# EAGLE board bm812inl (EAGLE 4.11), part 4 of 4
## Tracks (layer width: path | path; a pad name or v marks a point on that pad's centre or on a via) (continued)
N$167 (continued)
  Bottom 0.254: 107.99,116.19 98.46,116.19 97.51,117.14 C14.K1 | 107.99,116.19 108.94,117.14 C13.K1 | 120.69,116.19 121.64,117.14 C12.K1 | 120.69,116.19 107.99,116.19 | 133.39,116.19 134.34,117.14 C11.K1 | 133.39,116.19 120.69,116.19 | 146.09,116.19 147.04,117.14 C10.K1 | 146.09,116.19 133.39,116.19 | 158.79,116.19 159.74,117.14 C09.K1 | 146.09,116.19 158.79,116.19 | 171.49,116.19 172.44,117.14 C08.K1 | 158.79,116.19 171.49,116.19 | 184.19,116.19 185.14,117.14 C07.K1 | 171.49,116.19 184.19,116.19 | 196.89,116.19 197.84,117.14 C06.K1 | 184.19,116.19 196.89,116.19 | 209.59,116.19 210.54,117.14 C05.K1 | 196.89,116.19 209.59,116.19 | 222.29,116.19 223.24,117.14 C04.K1 | 209.59,116.19 222.29,116.19 | 234.99,116.19 235.94,117.14 C03.K1 | 222.29,116.19 234.99,116.19 | 247.69,116.19 248.64,117.14 C02.K1 | 234.99,116.19 247.69,116.19 | 247.69,116.19 260.39,116.19 261.34,117.14 C01.K1
N$168
  Bottom 0.254: 101.64,118.73 96.24,118.73 95.6,118.1 91.48,118.1 91.16,117.78 C14.K2 | 101.64,118.73 102.59,117.78 C13.K2 | 114.34,118.73 115.29,117.78 C12.K2 | 114.34,118.73 101.64,118.73 | 127.04,118.73 127.99,117.78 C11.K2 | 127.04,118.73 114.34,118.73 | 139.74,118.73 140.69,117.78 C10.K2 | 139.74,118.73 127.04,118.73 | 152.44,118.73 153.39,117.78 C09.K2 | 139.74,118.73 152.44,118.73 | 165.14,118.73 166.09,117.78 C08.K2 | 152.44,118.73 165.14,118.73 | 177.84,118.73 178.79,117.78 C07.K2 | 165.14,118.73 177.84,118.73 | 190.54,118.73 191.49,117.78 C06.K2 | 177.84,118.73 190.54,118.73 | 203.24,118.73 204.19,117.78 C05.K2 | 190.54,118.73 203.24,118.73 | 215.94,118.73 216.89,117.78 C04.K2 | 203.24,118.73 215.94,118.73 | 228.64,118.73 229.59,117.78 C03.K2 | 215.94,118.73 228.64,118.73 | 241.34,118.73 242.29,117.78 C02.K2 | 228.64,118.73 241.34,118.73 | 241.34,118.73 254.04,118.73 254.99,117.78 C01.K2
N$169
  Bottom 0.254: 104.81,113.02 95.29,113.02 94.33,113.97 C14.L1 | 104.81,113.02 105.76,113.97 C13.L1 | 117.51,113.02 118.46,113.97 C12.L1 | 117.51,113.02 104.81,113.02 | 130.21,113.02 131.16,113.97 C11.L1 | 130.21,113.02 117.51,113.02 | 142.91,113.02 143.86,113.97 C10.L1 | 142.91,113.02 130.21,113.02 | 155.61,113.02 156.56,113.97 C09.L1 | 142.91,113.02 155.61,113.02 | 168.31,113.02 169.26,113.97 C08.L1 | 155.61,113.02 168.31,113.02 | 181.01,113.02 181.96,113.97 C07.L1 | 168.31,113.02 181.01,113.02 | 193.71,113.02 194.66,113.97 C06.L1 | 181.01,113.02 193.71,113.02 | 206.41,113.02 207.36,113.97 C05.L1 | 193.71,113.02 206.41,113.02 | 219.11,113.02 220.06,113.97 C04.L1 | 206.41,113.02 219.11,113.02 | 231.81,113.02 232.76,113.97 C03.L1 | 219.11,113.02 231.81,113.02 | 244.51,113.02 245.46,113.97 C02.L1 | 231.81,113.02 244.51,113.02 | 244.51,113.02 257.21,113.02 258.16,113.97 C01.L1
N$170
  Bottom 0.254: C14.L2 87.98,114.61 88.94,115.56 97.83,115.56 98.78,114.61 99.41,114.61 C13.L2 104.49,114.29 105.76,115.56 114.34,115.56 | 114.34,115.56 113.38,114.61 C12.L2 | 123.86,115.56 114.34,115.56 | 123.86,115.56 124.81,114.61 C11.L2 | 136.56,115.56 137.51,114.61 C10.L2 | 136.56,115.56 123.86,115.56 | 149.26,115.56 150.21,114.61 C09.L2 | 149.26,115.56 136.56,115.56 | 161.96,115.56 162.91,114.61 C08.L2 | 149.26,115.56 161.96,115.56 | 174.66,115.56 175.61,114.61 C07.L2 | 161.96,115.56 174.66,115.56 | 187.36,115.56 188.31,114.61 C06.L2 | 174.66,115.56 187.36,115.56 | 200.06,115.56 201.01,114.61 C05.L2 | 187.36,115.56 200.06,115.56 | 212.76,115.56 213.71,114.61 C04.L2 | 200.06,115.56 212.76,115.56 | 225.46,115.56 226.41,114.61 C03.L2 | 212.76,115.56 225.46,115.56 | 238.16,115.56 239.11,114.61 C02.L2 | 225.46,115.56 238.16,115.56 | 238.16,115.56 250.86,115.56 251.81,114.61 C01.L2
N$171
  Bottom 0.254: 107.99,109.84 98.46,109.84 97.51,110.8 C14.M1 | 107.99,109.84 108.94,110.8 C13.M1 | 120.69,109.84 121.64,110.8 C12.M1 | 120.69,109.84 107.99,109.84 | 133.39,109.84 134.34,110.8 C11.M1 | 133.39,109.84 120.69,109.84 | 146.09,109.84 147.04,110.8 C10.M1 | 146.09,109.84 133.39,109.84 | 158.79,109.84 159.74,110.8 C09.M1 | 146.09,109.84 158.79,109.84 | 171.49,109.84 172.44,110.8 C08.M1 | 158.79,109.84 171.49,109.84 | 184.19,109.84 185.14,110.8 C07.M1 | 171.49,109.84 184.19,109.84 | 196.89,109.84 197.84,110.8 C06.M1 | 184.19,109.84 196.89,109.84 | 209.59,109.84 210.54,110.8 C05.M1 | 196.89,109.84 209.59,109.84 | 222.29,109.84 223.24,110.8 C04.M1 | 209.59,109.84 222.29,109.84 | 234.99,109.84 235.94,110.8 C03.M1 | 222.29,109.84 234.99,109.84 | 247.69,109.84 248.64,110.8 C02.M1 | 234.99,109.84 247.69,109.84 | 247.69,109.84 260.39,109.84 261.34,110.8 C01.M1
N$172
  Bottom 0.254: 101.64,112.38 96.24,112.38 95.29,111.43 91.16,111.43 C14.M2 | 101.64,112.38 102.59,111.43 C13.M2 | 114.34,112.38 115.29,111.43 C12.M2 | 114.34,112.38 101.64,112.38 | 127.04,112.38 127.99,111.43 C11.M2 | 127.04,112.38 114.34,112.38 | 139.74,112.38 140.69,111.43 C10.M2 | 139.74,112.38 127.04,112.38 | 152.44,112.38 153.39,111.43 C09.M2 | 152.44,112.38 139.74,112.38 | 165.14,112.38 166.09,111.43 C08.M2 | 152.44,112.38 165.14,112.38 | 177.84,112.38 178.79,111.43 C07.M2 | 165.14,112.38 177.84,112.38 | 190.54,112.38 191.49,111.43 C06.M2 | 177.84,112.38 190.54,112.38 | 203.24,112.38 204.19,111.43 C05.M2 | 190.54,112.38 203.24,112.38 | 215.94,112.38 216.89,111.43 C04.M2 | 203.24,112.38 215.94,112.38 | 228.64,112.38 229.59,111.43 C03.M2 | 215.94,112.38 228.64,112.38 | 241.34,112.38 242.29,111.43 C02.M2 | 228.64,112.38 241.34,112.38 | 241.34,112.38 254.04,112.38 254.99,111.43 C01.M2
N$175
  Bottom 0.254: 107.99,103.49 98.46,103.49 97.51,104.44 C14.P1 | 107.99,103.49 108.94,104.44 C13.P1 | 120.69,103.49 121.64,104.44 C12.P1 | 120.69,103.49 107.99,103.49 | 133.39,103.49 134.34,104.44 C11.P1 | 133.39,103.49 120.69,103.49 | 146.09,103.49 147.04,104.44 C10.P1 | 146.09,103.49 133.39,103.49 | 158.79,103.49 159.74,104.44 C09.P1 | 158.79,103.49 146.09,103.49 | 171.49,103.49 172.44,104.44 C08.P1 | 158.79,103.49 171.49,103.49 | 184.19,103.49 185.14,104.44 C07.P1 | 171.49,103.49 184.19,103.49 | 196.89,103.49 197.84,104.44 C06.P1 | 184.19,103.49 196.89,103.49 | 209.59,103.49 210.54,104.44 C05.P1 | 196.89,103.49 209.59,103.49 | 222.29,103.49 223.24,104.44 C04.P1 | 209.59,103.49 222.29,103.49 | 234.99,103.49 235.94,104.44 C03.P1 | 222.29,103.49 234.99,103.49 | 247.69,103.49 248.64,104.44 C02.P1 | 234.99,103.49 247.69,103.49 | 247.69,103.49 260.39,103.49 261.34,104.44 C01.P1
N$176
  Bottom 0.254: 101.64,106.03 92.11,106.03 91.16,105.08 C14.P2 | 101.64,106.03 102.59,105.08 C13.P2 | 114.34,106.03 115.29,105.08 C12.P2 | 114.34,106.03 101.64,106.03 | 127.04,106.03 127.99,105.08 C11.P2 | 127.04,106.03 114.34,106.03 | 139.74,106.03 140.69,105.08 C10.P2 | 139.74,106.03 127.04,106.03 | 152.44,106.03 153.39,105.08 C09.P2 | 152.44,106.03 139.74,106.03 | 165.14,106.03 166.09,105.08 C08.P2 | 152.44,106.03 165.14,106.03 | 177.84,106.03 178.79,105.08 C07.P2 | 165.14,106.03 177.84,106.03 | 190.54,106.03 191.49,105.08 C06.P2 | 177.84,106.03 190.54,106.03 | 203.24,106.03 204.19,105.08 C05.P2 | 190.54,106.03 203.24,106.03 | 215.94,106.03 216.89,105.08 C04.P2 | 203.24,106.03 215.94,106.03 | 228.64,106.03 229.59,105.08 C03.P2 | 215.94,106.03 228.64,106.03 | 241.34,106.03 242.29,105.08 C02.P2 | 228.64,106.03 241.34,106.03 | 241.34,106.03 254.04,106.03 254.99,105.08 C01.P2
N$177
  Bottom 0.254: 104.81,100.32 95.29,100.32 94.33,101.27 C14.R1 | 104.81,100.32 105.76,101.27 C13.R1 | 117.51,100.32 118.46,101.27 C12.R1 | 117.51,100.32 104.81,100.32 | 130.21,100.32 131.16,101.27 C11.R1 | 130.21,100.32 117.51,100.32 | 142.91,100.32 143.86,101.27 C10.R1 | 142.91,100.32 130.21,100.32 | 155.61,100.32 156.56,101.27 C09.R1 | 155.61,100.32 142.91,100.32 | 168.31,100.32 169.26,101.27 C08.R1 | 155.61,100.32 168.31,100.32 | 181.01,100.32 181.96,101.27 C07.R1 | 168.31,100.32 181.01,100.32 | 193.71,100.32 194.66,101.27 C06.R1 | 181.01,100.32 193.71,100.32 | 206.41,100.32 207.36,101.27 C05.R1 | 193.71,100.32 206.41,100.32 | 219.11,100.32 220.06,101.27 C04.R1 | 206.41,100.32 219.11,100.32 | 231.81,100.32 232.76,101.27 C03.R1 | 219.11,100.32 231.81,100.32 | 244.51,100.32 245.46,101.27 C02.R1 | 231.81,100.32 244.51,100.32 | 244.51,100.32 257.21,100.32 258.16,101.27 C01.R1
N$178
  Bottom 0.254: 98.46,102.86 88.94,102.86 87.98,101.91 C14.R2 | 98.46,102.86 99.41,101.91 C13.R2 | 111.16,102.86 112.11,101.91 C12.R2 | 111.16,102.86 98.46,102.86 | 123.86,102.86 124.81,101.91 C11.R2 | 123.86,102.86 111.16,102.86 | 136.56,102.86 137.51,101.91 C10.R2 | 136.56,102.86 123.86,102.86 | 149.26,102.86 150.21,101.91 C09.R2 | 149.26,102.86 136.56,102.86 | 161.96,102.86 162.91,101.91 C08.R2 | 161.96,102.86 149.26,102.86 | 174.66,102.86 175.61,101.91 C07.R2 | 161.96,102.86 174.66,102.86 | 187.36,102.86 188.31,101.91 C06.R2 | 174.66,102.86 187.36,102.86 | 200.06,102.86 201.01,101.91 C05.R2 | 187.36,102.86 200.06,102.86 | 212.76,102.86 213.71,101.91 C04.R2 | 200.06,102.86 212.76,102.86 | 225.46,102.86 226.41,101.91 C03.R2 | 212.76,102.86 225.46,102.86 | 238.16,102.86 239.11,101.91 C02.R2 | 225.46,102.86 238.16,102.86 | 238.16,102.86 250.86,102.86 251.81,101.91 C01.R2
N$179
  Bottom 0.254: 107.99,97.14 98.46,97.14 97.51,98.1 C14.S1 | 107.99,97.14 108.94,98.1 C13.S1 | 120.69,97.14 121.64,98.1 C12.S1 | 120.69,97.14 107.99,97.14 | 133.39,97.14 134.34,98.1 C11.S1 | 133.39,97.14 120.69,97.14 | 146.09,97.14 147.04,98.1 C10.S1 | 146.09,97.14 133.39,97.14 | 158.79,97.14 159.74,98.1 C09.S1 | 158.79,97.14 146.09,97.14 | 171.49,97.14 172.44,98.1 C08.S1 | 158.79,97.14 171.49,97.14 | 184.19,97.14 185.14,98.1 C07.S1 | 171.49,97.14 184.19,97.14 | 196.89,97.14 197.84,98.1 C06.S1 | 184.19,97.14 196.89,97.14 | 209.59,97.14 210.54,98.1 C05.S1 | 196.89,97.14 209.59,97.14 | 222.29,97.14 223.24,98.1 C04.S1 | 209.59,97.14 222.29,97.14 | 234.99,97.14 235.94,98.1 C03.S1 | 222.29,97.14 234.99,97.14 | 247.69,97.14 248.64,98.1 C02.S1 | 234.99,97.14 247.69,97.14 | 247.69,97.14 260.39,97.14 261.34,98.1 C01.S1
N$180
  Bottom 0.254: 101.64,99.68 92.11,99.68 91.16,98.73 C14.S2 | 101.64,99.68 102.59,98.73 C13.S2 | 114.34,99.68 115.29,98.73 C12.S2 | 114.34,99.68 101.64,99.68 | 127.04,99.68 127.99,98.73 C11.S2 | 127.04,99.68 114.34,99.68 | 139.74,99.68 140.69,98.73 C10.S2 | 139.74,99.68 127.04,99.68 | 152.44,99.68 153.39,98.73 C09.S2 | 152.44,99.68 139.74,99.68 | 165.14,99.68 166.09,98.73 C08.S2 | 165.14,99.68 152.44,99.68 | 177.84,99.68 178.79,98.73 C07.S2 | 165.14,99.68 177.84,99.68 | 190.54,99.68 191.49,98.73 C06.S2 | 177.84,99.68 190.54,99.68 | 203.24,99.68 204.19,98.73 C05.S2 | 190.54,99.68 203.24,99.68 | 215.94,99.68 216.89,98.73 C04.S2 | 203.24,99.68 215.94,99.68 | 228.64,99.68 229.59,98.73 C03.S2 | 215.94,99.68 228.64,99.68 | 241.34,99.68 242.29,98.73 C02.S2 | 228.64,99.68 241.34,99.68 | 241.34,99.68 254.04,99.68 254.99,98.73 C01.S2
N$183
  Bottom 0.254: 107.99,90.79 98.46,90.79 97.51,91.74 C14.U1 | 107.99,90.79 108.94,91.74 C13.U1 | 120.69,90.79 121.64,91.74 C12.U1 | 120.69,90.79 107.99,90.79 | 133.39,90.79 134.34,91.74 C11.U1 | 133.39,90.79 120.69,90.79 | 146.09,90.79 147.04,91.74 C10.U1 | 146.09,90.79 133.39,90.79 | 158.79,90.79 159.74,91.74 C09.U1 | 158.79,90.79 146.09,90.79 | 171.49,90.79 172.44,91.74 C08.U1 | 171.49,90.79 158.79,90.79 | 184.19,90.79 185.14,91.74 C07.U1 | 171.49,90.79 184.19,90.79 | 196.89,90.79 197.84,91.74 C06.U1 | 184.19,90.79 196.89,90.79 | 209.59,90.79 210.54,91.74 C05.U1 | 196.89,90.79 209.59,90.79 | 222.29,90.79 223.24,91.74 C04.U1 | 209.59,90.79 222.29,90.79 | 234.99,90.79 235.94,91.74 C03.U1 | 222.29,90.79 234.99,90.79 | 247.69,90.79 248.64,91.74 C02.U1 | 234.99,90.79 247.69,90.79 | 247.69,90.79 260.39,90.79 261.34,91.74 C01.U1
N$184
  Bottom 0.254: 101.64,93.33 92.11,93.33 91.16,92.38 C14.U2 | 101.64,93.33 102.59,92.38 C13.U2 | 101.64,93.33 114.34,93.33 115.29,92.38 C12.U2 116.56,92.38 117.51,93.33 127.04,93.33 | 127.04,93.33 127.99,92.38 C11.U2 | 139.74,93.33 140.69,92.38 C10.U2 | 139.74,93.33 127.04,93.33 | 152.44,93.33 153.39,92.38 C09.U2 | 152.44,93.33 139.74,93.33 | 165.14,93.33 166.09,92.38 C08.U2 | 165.14,93.33 152.44,93.33 | 177.84,93.33 178.79,92.38 C07.U2 | 165.14,93.33 177.84,93.33 | 190.54,93.33 191.49,92.38 C06.U2 | 177.84,93.33 190.54,93.33 | 203.24,93.33 204.19,92.38 C05.U2 | 190.54,93.33 203.24,93.33 | 215.94,93.33 216.89,92.38 C04.U2 | 203.24,93.33 215.94,93.33 | 228.64,93.33 229.59,92.38 C03.U2 | 215.94,93.33 228.64,93.33 | 241.34,93.33 242.29,92.38 C02.U2 | 228.64,93.33 241.34,93.33 | 241.34,93.33 254.04,93.33 254.99,92.38 C01.U2
N$186
  Bottom 0.254: 104.81,87.62 95.29,87.62 94.33,88.57 C14.V1 | 104.81,87.62 105.76,88.57 C13.V1 | 117.51,87.62 118.46,88.57 C12.V1 | 117.51,87.62 104.81,87.62 | 130.21,87.62 131.16,88.57 C11.V1 | 130.21,87.62 117.51,87.62 | 142.91,87.62 143.86,88.57 C10.V1 | 142.91,87.62 130.21,87.62 | 155.61,87.62 156.56,88.57 C09.V1 | 155.61,87.62 142.91,87.62 | 168.31,87.62 169.26,88.57 C08.V1 | 168.31,87.62 155.61,87.62 | 181.01,87.62 181.96,88.57 C07.V1 | 168.31,87.62 181.01,87.62 | 193.71,87.62 194.66,88.57 C06.V1 | 181.01,87.62 193.71,87.62 | 206.41,87.62 207.36,88.57 C05.V1 | 193.71,87.62 206.41,87.62 | 219.11,87.62 220.06,88.57 C04.V1 | 206.41,87.62 219.11,87.62 | 231.81,87.62 232.76,88.57 C03.V1 | 219.11,87.62 231.81,87.62 | 244.51,87.62 245.46,88.57 C02.V1 | 231.81,87.62 244.51,87.62 | 244.51,87.62 257.21,87.62 258.16,88.57 C01.V1
N$187
  Bottom 0.254: 98.46,90.16 93.06,90.16 92.11,89.21 87.98,89.21 C14.V2 | 98.46,90.16 99.41,89.21 C13.V2 | 111.16,90.16 112.11,89.21 C12.V2 | 111.16,90.16 98.46,90.16 | 123.86,90.16 124.81,89.21 C11.V2 | 123.86,90.16 111.16,90.16 | 136.56,90.16 137.51,89.21 C10.V2 | 136.56,90.16 123.86,90.16 | 149.26,90.16 150.21,89.21 C09.V2 | 149.26,90.16 136.56,90.16 | 161.96,90.16 162.91,89.21 C08.V2 | 161.96,90.16 149.26,90.16 | 174.66,90.16 175.61,89.21 C07.V2 | 174.66,90.16 161.96,90.16 | 187.36,90.16 188.31,89.21 C06.V2 | 174.66,90.16 187.36,90.16 | 200.06,90.16 201.01,89.21 C05.V2 | 187.36,90.16 200.06,90.16 | 212.76,90.16 213.71,89.21 C04.V2 | 200.06,90.16 212.76,90.16 | 225.46,90.16 226.41,89.21 C03.V2 | 212.76,90.16 225.46,90.16 | 238.16,90.16 239.11,89.21 C02.V2 | 225.46,90.16 238.16,90.16 | 238.16,90.16 250.86,90.16 251.81,89.21 C01.V2
N$188
  Bottom 0.254: 107.99,74.28 98.46,74.28 97.51,73.33 D14.A1 | 107.99,74.28 108.94,73.33 D13.A1 | 120.69,74.28 121.64,73.33 D12.A1 | 120.69,74.28 107.99,74.28 | 133.39,74.28 134.34,73.33 D11.A1 | 133.39,74.28 120.69,74.28 | 146.09,74.28 147.04,73.33 D10.A1 | 146.09,74.28 133.39,74.28 | 158.79,74.28 159.74,73.33 D09.A1 | 158.79,74.28 146.09,74.28 | 158.79,74.28 171.49,74.28 172.44,73.33 D08.A1 173.71,72.69 174.66,71.74 184.19,71.74 | 184.19,71.74 185.14,72.69 D07.A1 | 196.89,71.74 197.84,72.69 D06.A1 | 184.19,71.74 196.89,71.74 | 196.89,71.74 209.59,71.74 210.54,72.69 D05.A1 211.81,73.33 212.76,74.28 222.29,74.28 | 222.29,74.28 223.24,73.33 D04.A1 | 234.99,74.28 235.94,73.33 D03.A1 | 222.29,74.28 234.99,74.28 | 247.69,74.28 248.64,73.33 D02.A1 | 234.99,74.28 247.69,74.28 | 247.69,74.28 260.39,74.28 261.34,73.33 D01.A1
N$190
  Bottom 0.254: 104.81,71.11 95.29,71.11 94.33,70.16 D14.B1 | 104.81,71.11 105.76,70.16 D13.B1 | 104.81,71.11 117.51,71.11 118.46,70.16 D12.B1 119.73,70.16 122.59,70.16 123.54,71.11 130.21,71.11 131.16,70.16 D11.B1 132.43,70.16 135.29,70.16 136.24,71.11 142.91,71.11 143.86,70.16 D10.B1 145.13,70.16 147.99,70.16 148.94,71.11 155.61,71.11 156.56,70.16 D09.B1 157.83,70.16 158.47,70.79 162.6,70.79 162.91,71.11 171.49,71.11 | 171.49,71.11 170.53,70.16 D08.B1 | 181.01,71.11 171.49,71.11 | 181.01,71.11 181.96,70.16 D07.B1 | 193.71,71.11 194.66,70.16 D06.B1 | 193.71,71.11 181.01,71.11 | 206.41,71.11 207.36,70.16 D05.B1 | 193.71,71.11 206.41,71.11 | 206.41,71.11 219.11,71.11 220.06,70.16 D04.B1 221.33,70.16 224.19,70.16 225.14,71.11 231.81,71.11 232.76,70.16 D03.B1 234.03,70.16 236.89,70.16 237.84,71.11 244.51,71.11 245.46,70.16 D02.B1 246.73,70.16 249.59,70.16 250.54,71.11 257.21,71.11 258.16,70.16 D01.B1
N$196
  Bottom 0.254: 98.46,64.76 88.94,64.76 87.98,63.81 D14.D2 | 98.46,64.76 99.41,63.81 D13.D2 | 111.16,64.76 112.11,63.81 D12.D2 | 111.16,64.76 98.46,64.76 | 123.86,64.76 124.81,63.81 D11.D2 | 123.86,64.76 111.16,64.76 | 136.56,64.76 137.51,63.81 D10.D2 | 136.56,64.76 123.86,64.76 | 136.56,64.76 149.26,64.76 150.21,63.81 D09.D2 151.48,63.81 152.44,64.76 161.96,64.76 | 161.96,64.76 162.91,63.81 D08.D2 | 174.66,64.76 175.61,63.81 D07.D2 | 174.66,64.76 161.96,64.76 | 187.36,64.76 188.31,63.81 D06.D2 | 187.36,64.76 174.66,64.76 | 200.06,64.76 201.01,63.81 D05.D2 | 200.06,64.76 187.36,64.76 | 212.76,64.76 213.71,63.81 D04.D2 | 200.06,64.76 212.76,64.76 | 225.46,64.76 226.41,63.81 D03.D2 | 212.76,64.76 225.46,64.76 | 238.16,64.76 239.11,63.81 D02.D2 | 225.46,64.76 238.16,64.76 | 238.16,64.76 250.86,64.76 251.81,63.81 D01.D2
N$198
  Bottom 0.254: 101.64,61.58 92.11,61.58 91.16,60.63 D14.E2 | 101.64,61.58 102.59,60.63 D13.E2 | 114.34,61.58 115.29,60.63 D12.E2 | 114.34,61.58 101.64,61.58 | 127.04,61.58 127.99,60.63 D11.E2 | 127.04,61.58 114.34,61.58 | 139.74,61.58 140.69,60.63 D10.E2 | 139.74,61.58 127.04,61.58 | 152.44,61.58 153.39,60.63 D09.E2 | 152.44,61.58 139.74,61.58 | 165.14,61.58 166.09,60.63 D08.E2 | 165.14,61.58 152.44,61.58 | 177.84,61.58 178.79,60.63 D07.E2 | 177.84,61.58 165.14,61.58 | 190.54,61.58 191.49,60.63 D06.E2 | 190.54,61.58 177.84,61.58 | 203.24,61.58 204.19,60.63 D05.E2 | 203.24,61.58 190.54,61.58 | 215.94,61.58 216.89,60.63 D04.E2 | 203.24,61.58 215.94,61.58 | 228.64,61.58 229.59,60.63 D03.E2 | 215.94,61.58 228.64,61.58 | 241.34,61.58 242.29,60.63 D02.E2 | 228.64,61.58 241.34,61.58 | 241.34,61.58 254.04,61.58 254.99,60.63 D01.E2
N$202
  Bottom 0.254: D14.H2 91.16,54.28 91.48,54.6 95.6,54.6 96.24,55.23 101.64,55.23 102.59,54.28 D13.H2 103.86,54.28 104.81,55.23 114.34,55.23 | 114.34,55.23 115.29,54.28 D12.H2 | 127.04,55.23 127.99,54.28 D11.H2 | 127.04,55.23 114.34,55.23 | 139.74,55.23 140.69,54.28 D10.H2 | 139.74,55.23 127.04,55.23 | 152.44,55.23 153.39,54.28 D09.H2 | 152.44,55.23 139.74,55.23 | 165.14,55.23 166.09,54.28 D08.H2 | 165.14,55.23 152.44,55.23 | 177.84,55.23 178.79,54.28 D07.H2 | 177.84,55.23 165.14,55.23 | 190.54,55.23 191.49,54.28 D06.H2 | 190.54,55.23 177.84,55.23 | 203.24,55.23 204.19,54.28 D05.H2 | 203.24,55.23 190.54,55.23 | 215.94,55.23 216.89,54.28 D04.H2 | 203.24,55.23 215.94,55.23 | 228.64,55.23 229.59,54.28 D03.H2 | 215.94,55.23 228.64,55.23 | 241.34,55.23 242.29,54.28 D02.H2 | 228.64,55.23 241.34,55.23 | 241.34,55.23 254.04,55.23 254.99,54.28 D01.H2
N$204
  Bottom 0.254: 98.46,52.06 88.94,52.06 87.98,51.1 D14.J2 | 98.46,52.06 99.41,51.1 D13.J2 | 111.16,52.06 112.11,51.1 D12.J2 | 111.16,52.06 98.46,52.06 | 123.86,52.06 124.81,51.1 D11.J2 | 123.86,52.06 111.16,52.06 | 136.56,52.06 137.51,51.1 D10.J2 | 136.56,52.06 123.86,52.06 | 149.26,52.06 150.21,51.1 D09.J2 | 149.26,52.06 136.56,52.06 | 161.96,52.06 162.91,51.1 D08.J2 | 161.96,52.06 149.26,52.06 | 174.66,52.06 175.61,51.1 D07.J2 | 174.66,52.06 161.96,52.06 | 187.36,52.06 188.31,51.1 D06.J2 | 187.36,52.06 174.66,52.06 | 200.06,52.06 201.01,51.1 D05.J2 | 200.06,52.06 187.36,52.06 | 212.76,52.06 213.71,51.1 D04.J2 | 212.76,52.06 200.06,52.06 | 225.46,52.06 226.41,51.1 D03.J2 | 212.76,52.06 225.46,52.06 | 238.16,52.06 239.11,51.1 D02.J2 | 225.46,52.06 238.16,52.06 | 238.16,52.06 250.86,52.06 251.81,51.1 D01.J2
N$206
  Bottom 0.254: 101.64,46.34 92.11,46.34 91.16,47.29 D14.K2 | 101.64,46.34 102.59,47.29 D13.K2 | 114.34,46.34 115.29,47.29 D12.K2 | 114.34,46.34 101.64,46.34 | 127.04,46.34 127.99,47.29 D11.K2 | 127.04,46.34 114.34,46.34 | 139.74,46.34 140.69,47.29 D10.K2 | 139.74,46.34 127.04,46.34 | 152.44,46.34 153.39,47.29 D09.K2 | 152.44,46.34 139.74,46.34 | 165.14,46.34 166.09,47.29 D08.K2 | 165.14,46.34 152.44,46.34 | 177.84,46.34 178.79,47.29 D07.K2 | 177.84,46.34 165.14,46.34 | 190.54,46.34 191.49,47.29 D06.K2 | 190.54,46.34 177.84,46.34 | 203.24,46.34 204.19,47.29 D05.K2 | 203.24,46.34 190.54,46.34 | 215.94,46.34 216.89,47.29 D04.K2 | 215.94,46.34 203.24,46.34 | 228.64,46.34 229.59,47.29 D03.K2 | 215.94,46.34 228.64,46.34 | 241.34,46.34 242.29,47.29 D02.K2 | 228.64,46.34 241.34,46.34 | 241.34,46.34 254.04,46.34 254.99,47.29 D01.K2
N$208
  Bottom 0.254: 98.46,45.71 88.94,45.71 87.98,44.75 D14.L2 | 98.46,45.71 99.41,44.75 D13.L2 | 111.16,45.71 112.11,44.75 D12.L2 | 111.16,45.71 98.46,45.71 | 123.86,45.71 124.81,44.75 D11.L2 | 123.86,45.71 111.16,45.71 | 136.56,45.71 137.51,44.75 D10.L2 | 136.56,45.71 123.86,45.71 | 149.26,45.71 150.21,44.75 D09.L2 | 149.26,45.71 136.56,45.71 | 161.96,45.71 162.91,44.75 D08.L2 | 161.96,45.71 149.26,45.71 | 174.66,45.71 175.61,44.75 D07.L2 | 174.66,45.71 161.96,45.71 | 187.36,45.71 188.31,44.75 D06.L2 | 187.36,45.71 174.66,45.71 | 200.06,45.71 201.01,44.75 D05.L2 | 200.06,45.71 187.36,45.71 | 212.76,45.71 213.71,44.75 D04.L2 | 212.76,45.71 200.06,45.71 | 225.46,45.71 226.41,44.75 D03.L2 | 212.76,45.71 225.46,45.71 | 238.16,45.71 239.11,44.75 D02.L2 | 225.46,45.71 238.16,45.71 | 238.16,45.71 250.86,45.71 251.81,44.75 D01.L2
N$210
  Bottom 0.254: 101.64,42.53 96.24,42.53 95.6,41.9 91.48,41.9 91.16,41.58 D14.M2 | 101.64,42.53 102.59,41.58 D13.M2 | 114.34,42.53 115.29,41.58 D12.M2 | 114.34,42.53 101.64,42.53 | 127.04,42.53 127.99,41.58 D11.M2 | 127.04,42.53 114.34,42.53 | 139.74,42.53 140.69,41.58 D10.M2 | 139.74,42.53 127.04,42.53 | 152.44,42.53 153.39,41.58 D09.M2 | 152.44,42.53 139.74,42.53 | 165.14,42.53 166.09,41.58 D08.M2 | 165.14,42.53 152.44,42.53 | 177.84,42.53 178.79,41.58 D07.M2 | 177.84,42.53 165.14,42.53 | 190.54,42.53 191.49,41.58 D06.M2 | 190.54,42.53 177.84,42.53 | 203.24,42.53 204.19,41.58 D05.M2 | 203.24,42.53 190.54,42.53 | 215.94,42.53 216.89,41.58 D04.M2 | 215.94,42.53 203.24,42.53 | 228.64,42.53 229.59,41.58 D03.M2 | 215.94,42.53 228.64,42.53 | 241.34,42.53 242.29,41.58 D02.M2 | 228.64,42.53 241.34,42.53 | 241.34,42.53 254.04,42.53 254.99,41.58 D01.M2
N$214
  Bottom 0.254: 101.64,36.18 92.11,36.18 91.16,35.23 D14.P2 | 101.64,36.18 102.59,35.23 D13.P2 | 101.64,36.18 114.34,36.18 115.29,35.23 D12.P2 116.56,35.23 116.88,35.55 121,35.55 121.64,36.18 130.21,36.18 | 130.21,36.18 129.26,35.23 D11.P2 | 139.74,36.18 130.21,36.18 | 139.74,36.18 140.69,35.23 D10.P2 | 152.44,36.18 153.39,35.23 D09.P2 | 152.44,36.18 139.74,36.18 | 165.14,36.18 166.09,35.23 D08.P2 | 165.14,36.18 152.44,36.18 | 177.84,36.18 178.79,35.23 D07.P2 | 177.84,36.18 165.14,36.18 | 190.54,36.18 191.49,35.23 D06.P2 | 190.54,36.18 177.84,36.18 | 203.24,36.18 204.19,35.23 D05.P2 | 203.24,36.18 190.54,36.18 | 215.94,36.18 216.89,35.23 D04.P2 | 215.94,36.18 203.24,36.18 | 228.64,36.18 229.59,35.23 D03.P2 | 228.64,36.18 215.94,36.18 | 241.34,36.18 242.29,35.23 D02.P2 | 228.64,36.18 241.34,36.18 | 241.34,36.18 254.04,36.18 254.99,35.23 D01.P2
N$215
  Bottom 0.254: 104.81,30.47 95.29,30.47 94.33,31.42 D14.R1 | 104.81,30.47 105.76,31.42 D13.R1 | 117.51,30.47 118.46,31.42 D12.R1 | 117.51,30.47 104.81,30.47 | 130.21,30.47 131.16,31.42 D11.R1 | 130.21,30.47 117.51,30.47 | 142.91,30.47 143.86,31.42 D10.R1 | 142.91,30.47 130.21,30.47 | 155.61,30.47 156.56,31.42 D09.R1 | 155.61,30.47 142.91,30.47 | 168.31,30.47 169.26,31.42 D08.R1 | 168.31,30.47 155.61,30.47 | 181.01,30.47 181.96,31.42 D07.R1 | 181.01,30.47 168.31,30.47 | 193.71,30.47 194.66,31.42 D06.R1 | 193.71,30.47 181.01,30.47 | 206.41,30.47 207.36,31.42 D05.R1 | 206.41,30.47 193.71,30.47 | 219.11,30.47 220.06,31.42 D04.R1 | 219.11,30.47 206.41,30.47 | 231.81,30.47 232.76,31.42 D03.R1 | 231.81,30.47 219.11,30.47 | 244.51,30.47 245.46,31.42 D02.R1 | 231.81,30.47 244.51,30.47 | 244.51,30.47 257.21,30.47 258.16,31.42 D01.R1
N$216
  Bottom 0.254: 98.46,33.01 88.94,33.01 87.98,32.06 D14.R2 | 98.46,33.01 99.41,32.06 D13.R2 | 111.16,33.01 112.11,32.06 D12.R2 | 111.16,33.01 98.46,33.01 | 123.86,33.01 124.81,32.06 D11.R2 | 123.86,33.01 111.16,33.01 | 136.56,33.01 137.51,32.06 D10.R2 | 136.56,33.01 123.86,33.01 | 149.26,33.01 150.21,32.06 D09.R2 | 149.26,33.01 136.56,33.01 | 161.96,33.01 162.91,32.06 D08.R2 | 161.96,33.01 149.26,33.01 | 174.66,33.01 175.61,32.06 D07.R2 | 174.66,33.01 161.96,33.01 | 187.36,33.01 188.31,32.06 D06.R2 | 187.36,33.01 174.66,33.01 | 200.06,33.01 201.01,32.06 D05.R2 | 200.06,33.01 187.36,33.01 | 212.76,33.01 213.71,32.06 D04.R2 | 212.76,33.01 200.06,33.01 | 225.46,33.01 226.41,32.06 D03.R2 | 225.46,33.01 212.76,33.01 | 238.16,33.01 239.11,32.06 D02.R2 | 225.46,33.01 238.16,33.01 | 238.16,33.01 250.86,33.01 251.81,32.06 D01.R2
N$218
  Bottom 0.254: 101.64,29.83 92.11,29.83 91.16,28.88 D14.S2 | 101.64,29.83 102.59,28.88 D13.S2 | 114.34,29.83 115.29,28.88 D12.S2 | 114.34,29.83 101.64,29.83 | 127.04,29.83 127.99,28.88 D11.S2 | 127.04,29.83 114.34,29.83 | 139.74,29.83 140.69,28.88 D10.S2 | 139.74,29.83 127.04,29.83 | 152.44,29.83 153.39,28.88 D09.S2 | 152.44,29.83 139.74,29.83 | 165.14,29.83 166.09,28.88 D08.S2 | 165.14,29.83 152.44,29.83 | 177.84,29.83 178.79,28.88 D07.S2 | 177.84,29.83 165.14,29.83 | 190.54,29.83 191.49,28.88 D06.S2 | 190.54,29.83 177.84,29.83 | 203.24,29.83 204.19,28.88 D05.S2 | 203.24,29.83 190.54,29.83 | 215.94,29.83 216.89,28.88 D04.S2 | 215.94,29.83 203.24,29.83 | 228.64,29.83 229.59,28.88 D03.S2 | 228.64,29.83 215.94,29.83 | 241.34,29.83 242.29,28.88 D02.S2 | 228.64,29.83 241.34,29.83 | 241.34,29.83 254.04,29.83 254.99,28.88 D01.S2
N$221
  Bottom 0.254: 107.99,23.48 98.46,23.48 97.51,22.53 D14.U1 | 107.99,23.48 108.94,22.53 D13.U1 | 120.69,23.48 121.64,22.53 D12.U1 | 120.69,23.48 107.99,23.48 | 133.39,23.48 134.34,22.53 D11.U1 | 133.39,23.48 120.69,23.48 | 146.09,23.48 147.04,22.53 D10.U1 | 146.09,23.48 133.39,23.48 | 158.79,23.48 159.74,22.53 D09.U1 | 158.79,23.48 146.09,23.48 | 171.49,23.48 172.44,22.53 D08.U1 | 171.49,23.48 158.79,23.48 | 184.19,23.48 185.14,22.53 D07.U1 | 184.19,23.48 171.49,23.48 | 196.89,23.48 197.84,22.53 D06.U1 | 196.89,23.48 184.19,23.48 | 209.59,23.48 210.54,22.53 D05.U1 | 209.59,23.48 196.89,23.48 | 222.29,23.48 223.24,22.53 D04.U1 | 222.29,23.48 209.59,23.48 | 234.99,23.48 235.94,22.53 D03.U1 | 234.99,23.48 222.29,23.48 | 247.69,23.48 248.64,22.53 D02.U1 | 234.99,23.48 247.69,23.48 | 247.69,23.48 260.39,23.48 261.34,22.53 D01.U1
N$222
  Bottom 0.254: 101.64,20.94 92.11,20.94 91.16,21.89 D14.U2 | 101.64,20.94 102.59,21.89 D13.U2 | 114.34,20.94 115.29,21.89 D12.U2 | 114.34,20.94 101.64,20.94 | 127.04,20.94 127.99,21.89 D11.U2 | 127.04,20.94 114.34,20.94 | 139.74,20.94 140.69,21.89 D10.U2 | 139.74,20.94 127.04,20.94 | 152.44,20.94 153.39,21.89 D09.U2 | 152.44,20.94 139.74,20.94 | 165.14,20.94 166.09,21.89 D08.U2 | 165.14,20.94 152.44,20.94 | 177.84,20.94 178.79,21.89 D07.U2 | 177.84,20.94 165.14,20.94 | 190.54,20.94 191.49,21.89 D06.U2 | 190.54,20.94 177.84,20.94 | 203.24,20.94 204.19,21.89 D05.U2 | 203.24,20.94 190.54,20.94 | 215.94,20.94 216.89,21.89 D04.U2 | 215.94,20.94 203.24,20.94 | 228.64,20.94 229.59,21.89 D03.U2 | 228.64,20.94 215.94,20.94 | 241.34,20.94 242.29,21.89 D02.U2 | 241.34,20.94 228.64,20.94 | 241.34,20.94 254.04,20.94 254.99,21.89 D01.U2
N$223
  Bottom 0.254: D14.V1 94.33,18.72 95.29,17.77 104.81,17.77 105.76,18.72 D13.V1 107.03,19.35 107.99,20.31 117.51,20.31 118.46,19.35 D12.V1 119.73,18.72 120.69,17.77 130.21,17.77 | 130.21,17.77 131.16,18.72 D11.V1 | 142.91,17.77 143.86,18.72 D10.V1 | 142.91,17.77 130.21,17.77 | 155.61,17.77 156.56,18.72 D09.V1 | 155.61,17.77 142.91,17.77 | 168.31,17.77 169.26,18.72 D08.V1 | 168.31,17.77 155.61,17.77 | 181.01,17.77 181.96,18.72 D07.V1 | 181.01,17.77 168.31,17.77 | 193.71,17.77 194.66,18.72 D06.V1 | 193.71,17.77 181.01,17.77 | 206.41,17.77 207.36,18.72 D05.V1 | 206.41,17.77 193.71,17.77 | 219.11,17.77 220.06,18.72 D04.V1 | 219.11,17.77 206.41,17.77 | 231.81,17.77 232.76,18.72 D03.V1 | 231.81,17.77 219.11,17.77 | 244.51,17.77 245.46,18.72 D02.V1 | 244.51,17.77 231.81,17.77 | 244.51,17.77 257.21,17.77 258.16,18.72 D01.V1
N$224
  Top 0.254: D13.V2 100.37,18.4 100.37,17.77 111.16,17.77 112.11,18.72 D12.V2 113.38,18.72 117.83,18.72 117.83,18.4 118.46,17.77 124.81,17.77 124.81,18.72 D11.V2 | D07.V2 176.57,18.4 176.57,17.77 183.23,17.77 183.87,18.4 183.87,18.72 188.31,18.72 D06.V2 189.27,18.4 189.27,17.77 195.93,17.77 196.57,18.4 196.57,18.72 201.01,18.72 D05.V2
  Bottom 0.254: 212.76,20.31 203.24,20.31 202.28,19.35 D05.V2 | 212.76,20.31 213.71,19.35 D04.V2 | 225.46,20.31 226.41,19.35 D03.V2 | 225.46,20.31 212.76,20.31 | 238.16,20.31 239.11,19.35 D02.V2 | 238.16,20.31 225.46,20.31 | 238.16,20.31 250.86,20.31 251.81,19.35 D01.V2 | D14.V2 87.98,19.35 88.94,20.31 98.46,20.31 99.41,19.35 D13.V2 | 136.56,20.31 127.04,20.31 126.08,19.35 D11.V2 | 136.56,20.31 137.51,19.35 D10.V2 | 149.26,20.31 150.21,19.35 D09.V2 | 149.26,20.31 136.56,20.31 | 161.96,20.31 162.91,19.35 D08.V2 | 161.96,20.31 149.26,20.31 | 161.96,20.31 174.66,20.31 175.61,19.35 D07.V2
VCC  (via drill 0.61)
  Top 0.635: v100.68,75.24 102.59,73.33 D13.A2 | D05.A2 205.46,72.69 209.59,72.69 209.59,72.38 210.54,71.43 216.89,71.43 216.89,72.69 D04.A2 | D08.A2 167.36,72.69 171.49,72.69 171.49,72.38 172.44,71.43 178.79,71.43 178.79,72.69 D07.A2 | v114.97,75.24 115.61,74.6 115.61,73.65 D12.A2 | C02.A2 242.29,142.55 238.16,142.55 238.16,142.23 237.21,141.27 230.54,141.27 230.54,142.23 C03.A2 | C08.A2 167.36,142.55 171.49,142.55 171.49,142.23 172.44,141.27 178.79,141.27 178.79,142.55 C07.A2 | v127.67,145.08 128.31,144.45 128.31,143.5 C11.A2 | D01.A2 255.94,73.65 263.56,81.27 263.56,137.15 258.16,142.55 256.26,142.55 C01.A2 | A13.A2 103.54,275.58 103.54,274.62 110.21,274.62 111.16,275.58 111.16,275.9 115.29,275.9 A12.A2 116.56,275.9 120.69,275.9 120.69,275.58 121.64,274.62 127.99,274.62 127.99,275.9 A11.A2 | A08.A2 167.36,275.9 171.49,275.9 171.49,275.58 172.44,274.62 178.79,274.62 178.79,275.9 A07.A2 | 231.81,204.77 230.54,204.77 230.54,205.73 B03.A2 | 231.81,204.77 237.21,204.77 238.16,205.73 238.16,206.05 242.29,206.05 B02.A2 243.24,205.73 243.24,204.77 249.91,204.77 250.86,205.73 250.86,206.05 254.99,206.05 B01.A2 | B08.A2 167.36,206.05 171.49,206.05 171.49,205.73 172.44,204.77 178.79,204.77 178.79,206.05 B07.A2 | B04.A2 216.89,206.05 212.76,206.05 212.76,205.73 211.81,204.77 205.14,204.77 205.14,205.73 B05.A2 | v101,208.27 102.59,206.68 B13.A2 | v115.92,208.58 B12.A2 | v128.31,208.58 128.31,207 B11.A2 | v141.32,208.58 B10.A2 | 231.81,204.77 231.81,274.31 230.54,275.58 A03.A2 | C09.A2 153.71,143.5 152.44,144.77 152.44,204.46 153.71,205.73 B09.A2
  Bottom 0.635: 50.68,74.44 51.79,73.33 D17.A2 | 50.68,74.44 50.52,74.6 41.63,74.6 40.36,73.33 D18.A2 | 63.38,74.44 63.22,74.6 50.84,74.6 50.68,74.44 | 63.38,74.44 64.49,73.33 D16.A2 | 63.38,74.44 63.54,74.6 75.92,74.6 77.19,73.33 D15.A2 78.46,73.33 79.73,73.33 81,74.6 88.62,74.6 89.89,73.33 D14.A2 91.16,73.33 92.75,74.92 100.37,74.92 v100.68,75.24 v114.97,75.24 | D12.A2 116.56,72.69 117.51,71.74 121.32,71.74 121.64,71.43 122.91,71.43 124.18,72.69 127.99,72.69 D11.A2 129.26,72.69 129.58,72.69 130.85,71.43 135.61,71.43 135.93,71.74 139.74,71.74 140.69,72.69 D10.A2 141.96,72.69 142.28,72.69 143.55,71.43 148.31,71.43 148.63,71.74 152.44,71.74 153.39,72.69 D09.A2 154.66,72.69 154.98,72.69 156.25,71.43 161.01,71.43 161.33,71.74 165.14,71.74 166.09,72.69 D08.A2 | 190.38,74.44 191.49,73.33 D06.A2 | 190.38,74.44 190.22,74.6 181.33,74.6 180.06,73.33 D07.A2 | D05.A2 204.19,73.33 202.92,74.6 190.54,74.6 190.38,74.44 | D04.A2 218.16,72.69 219.11,71.74 222.92,71.74 223.24,71.43 224.51,71.43 225.78,72.69 229.59,72.69 D03.A2 230.86,72.69 231.18,72.69 232.45,71.43 237.21,71.43 237.53,71.74 241.34,71.74 242.29,72.69 D02.A2 243.56,72.69 243.88,72.69 245.15,71.43 249.91,71.43 250.23,71.74 254.04,71.74 254.99,72.69 D01.A2 | 101.48,144.29 101.32,144.45 92.43,144.45 91.16,143.18 C14.A2 89.89,142.55 88.62,141.27 79.73,141.27 78.46,142.55 C15.A2 77.19,143.18 75.92,144.45 67.03,144.45 65.76,143.18 C16.A2 64.49,143.18 63.22,144.45 50.84,144.45 50.68,144.29 | 101.48,144.29 102.59,143.18 C13.A2 | 101.48,144.29 101.64,144.45 114.02,144.45 115.29,143.18 C12.A2 116.56,143.18 118.46,145.08 v127.67,145.08
  Bottom 0.635: 25.28,144.29 26.39,143.18 C19.A2 | 25.28,144.29 25.12,144.45 16.23,144.45 14.96,143.18 C20.A2 | 37.98,144.29 37.82,144.45 25.44,144.45 25.28,144.29 | 37.98,144.29 39.09,143.18 C18.A2 | 50.68,144.29 50.52,144.45 38.14,144.45 37.98,144.29 | 50.68,144.29 51.79,143.18 C17.A2 | C11.A2 129.26,142.55 130.21,141.59 134.02,141.59 134.34,141.27 135.61,141.27 136.88,142.55 140.69,142.55 C10.A2 141.96,142.55 142.28,142.55 143.55,141.27 148.31,141.27 148.63,141.59 152.44,141.59 153.39,142.55 C09.A2 154.66,142.55 154.98,142.55 156.25,141.27 161.01,141.27 161.33,141.59 165.14,141.59 166.09,142.55 C08.A2 | C02.A2 243.56,142.55 244.51,141.59 248.32,141.59 248.64,141.27 249.91,141.27 251.18,142.55 254.99,142.55 C01.A2 | 190.38,144.29 191.49,143.18 C06.A2 | 190.38,144.29 190.22,144.45 181.33,144.45 180.06,143.18 C07.A2 | 203.08,144.29 202.92,144.45 190.54,144.45 190.38,144.29 | 203.08,144.29 204.19,143.18 C05.A2 | 215.78,144.29 215.62,144.45 203.24,144.45 203.08,144.29 | 215.78,144.29 216.89,143.18 C04.A2 | C03.A2 229.59,143.18 228.32,144.45 215.94,144.45 215.78,144.29 | 88.78,274.78 89.89,275.9 A14.A2 | 88.78,274.78 88.62,274.62 79.73,274.62 78.46,275.9 A15.A2 | A13.A2 102.59,275.9 101.64,274.94 97.83,274.94 97.51,274.62 88.94,274.62 88.78,274.78 | A11.A2 129.26,275.9 130.21,274.94 134.02,274.94 134.34,274.62 135.61,274.62 136.88,275.9 140.69,275.9 A10.A2 141.96,275.9 142.28,275.9 143.55,274.62 148.31,274.62 148.63,274.94 152.44,274.94 153.39,275.9 A09.A2 154.66,275.9 154.98,275.9 156.25,274.62 161.01,274.62 161.33,274.94 165.14,274.94 166.09,275.9 A08.A2
  Bottom 0.635: +5V.1 267.37,281.93 261.66,281.93 256.26,276.53 A01.A2 254.99,276.53 253.72,277.8 241.34,277.8 241.18,277.64 | 190.38,277.64 191.49,276.53 A06.A2 | 190.38,277.64 190.22,277.8 181.33,277.8 180.06,276.53 A07.A2 | 203.08,277.64 202.92,277.8 190.54,277.8 190.38,277.64 | 203.08,277.64 204.19,276.53 A05.A2 | 215.78,277.64 215.62,277.8 203.24,277.8 203.08,277.64 | 215.78,277.64 216.89,276.53 A04.A2 | 228.48,277.64 228.32,277.8 215.94,277.8 215.78,277.64 | 228.48,277.64 229.59,276.53 A03.A2 | 241.18,277.64 241.02,277.8 228.64,277.8 228.48,277.64 | 241.18,277.64 242.29,276.53 A02.A2 | B04.A2 218.16,206.05 219.11,205.09 222.92,205.09 223.24,204.77 224.51,204.77 225.78,206.05 229.59,206.05 B03.A2 | B10.A2 141.96,206.05 142.91,205.09 146.72,205.09 147.04,204.77 148.31,204.77 149.58,206.05 153.39,206.05 B09.A2 154.66,206.05 154.98,206.05 156.25,204.77 161.01,204.77 161.33,205.09 165.14,205.09 166.09,206.05 B08.A2 | 190.38,207.79 191.49,206.68 B06.A2 | 190.38,207.79 190.22,207.95 181.33,207.95 180.06,206.68 B07.A2 | B05.A2 204.19,206.68 202.92,207.95 190.54,207.95 190.38,207.79 | B20.A2 14.96,206.68 16.23,207.95 25.12,207.95 26.39,206.68 B19.A2 27.66,206.68 29.25,208.27 37.5,208.27 39.09,206.68 B18.A2 40.36,206.68 41.63,207.95 50.52,207.95 51.79,206.68 B17.A2 53.06,206.68 54.65,208.27 62.9,208.27 64.49,206.68 B16.A2 65.76,206.68 67.03,207.95 75.92,207.95 76.08,207.79 | 76.08,207.79 77.19,206.68 B15.A2 | 88.78,207.79 88.62,207.95 76.24,207.95 76.08,207.79 | 88.78,207.79 89.89,206.68 B14.A2 | 88.78,207.79 88.94,207.95 100.68,207.95 v101,208.27 115.61,208.27 v115.92,208.58 v128.31,208.58 v141.32,208.58

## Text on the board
Top: 1 | A
Bottom: VRS | A | VRS
tPlace: 20 | 19 | 18 | 17 | 16 | 15 | 14 | 13 | 12 | 11 | 10 | 9 | 8 | 7 | 6 | 5 | 4 | 3 | 2 | 1 | Fold in ECOs. | A | B | C | D
bPlace: A | B | C | D | 11 | 20 | 19 | 18 | 17 | 16 | 15 | 14 | 13 | 12 | 10 | 9 | 8 | 7 | 6 | 5 | 4 | 3 | 2 | 1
